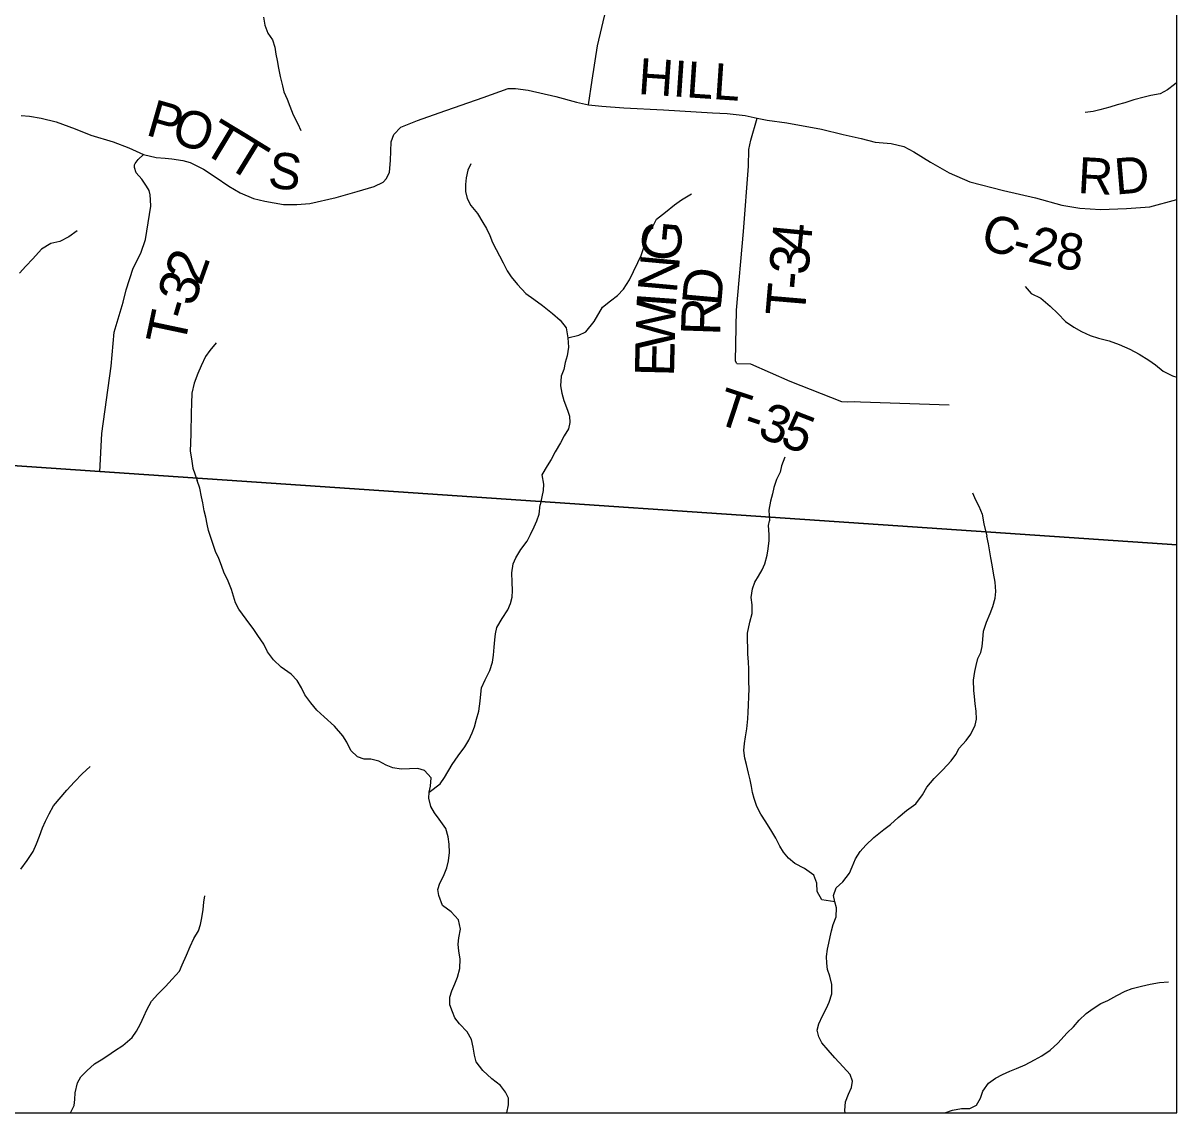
# Model space of a CAD drawing. Extents: x -139 to 835, y 0 to 440.
# Drawn here: x 550 to 607.6, y 185.1 to 239.4 of the extents above; entities that cross this region are included whole.
import ezdxf

# ---------------------------------------------------------------- set-up
doc = ezdxf.new("R2010")
doc.units = 0
for name, color, linetype in [('Default', 7, 'Continuous'), ('GM_X_County_Road', 7, 'Continuous'), ('GM_X_County_Road_Text', 7, 'Continuous'), ('GM_X_Minor_River', 7, 'Continuous'), ('GM_X_Township_Road', 7, 'Continuous'), ('GM_X_Township_Road_Text', 7, 'Continuous'), ('SH_Cut_Line', 7, 'Continuous')]:
    doc.layers.add(name, color=color, linetype=linetype)

msp = doc.modelspace()

# ---------------------------------------------------------------- linework, layer by layer
at = {"layer": 'Default'}
msp.add_lwpolyline([(533.705, 218.461), (553.865, 217.083), (607.596, 213.413), (607.596, 313.688), (599.523, 343.435), (599.103, 345.232), (598.348, 346.669), (593.771, 354.537), (573.292, 389.29), (556.01, 382.105), (544.238, 377.806)], dxfattribs=at)
msp.add_lwpolyline([(509.507, 185.075), (607.596, 185.075), (607.596, 213.413), (553.865, 217.083), (533.705, 218.461), (512.652, 220.106)], close=True, dxfattribs=at)
at = {"layer": 'GM_X_County_Road'}
msp.add_lwpolyline([(549.953, 234.836), (550.361, 234.805), (550.95, 234.711), (551.697, 234.514), (552.649, 234.171), (553.43, 233.859), (554.537, 233.522), (555.317, 233.224), (556.058, 232.895), (556.689, 232.74), (557.138, 232.704), (557.457, 232.675), (558.009, 232.591), (558.373, 232.484), (558.712, 232.328), (559.037, 232.161), (559.622, 231.779), (560.308, 231.311), (560.867, 230.977), (561.543, 230.702), (562.103, 230.559), (563.039, 230.392), (563.703, 230.392), (564.339, 230.448), (565.654, 230.742), (566.713, 231.051), (567.563, 231.302), (567.997, 231.508), (568.173, 231.699), (568.318, 232.009), (568.366, 232.597), (568.398, 233.525), (568.542, 233.893), (568.879, 234.261), (569.714, 234.585), (570.805, 234.968), (572.987, 235.734), (574.238, 236.176), (574.607, 236.19), (575.233, 236.102), (576.613, 235.778), (577.656, 235.498), (578.253, 235.362), (578.911, 235.303), (580.01, 235.222), (581.984, 235.126), (584.432, 234.964), (585.155, 234.929), (586.06, 234.833), (586.66, 234.71), (587.164, 234.597), (588.135, 234.466), (589.873, 234.151), (590.947, 233.882), (591.841, 233.688), (592.541, 233.509), (593.338, 233.435), (593.972, 233.285), (594.477, 233.031), (595.306, 232.509), (596.233, 231.971), (597.275, 231.524), (598.95, 231.091), (600.544, 230.732), (601.854, 230.363), (602.755, 230.212), (603.787, 230.151), (605.083, 230.192), (606.247, 230.282), (607.596, 230.652)], dxfattribs=at)
at = {"layer": 'GM_X_Minor_River'}
msp.add_line((607.596, 236.481), (607.475, 236.379), dxfattribs=at)
for points in [[(562.036, 239.735), (562.109, 239.351), (562.26, 238.941), (562.478, 238.615), (562.603, 238.242), (562.651, 237.894), (562.712, 237.581), (562.786, 237.197), (562.871, 236.776), (562.983, 236.319), (563.057, 236.018), (563.209, 235.657), (563.348, 235.307), (563.512, 234.874), (563.741, 234.416), (563.893, 234.09)], [(607.475, 236.379), (607.133, 236.119), (606.753, 235.919), (606.296, 235.828), (605.956, 235.76), (605.446, 235.621), (605.001, 235.47), (604.622, 235.366), (604.242, 235.251), (603.758, 235.124), (603.418, 235.031), (603.027, 234.988)], [(572.382, 232.427), (572.221, 232.117), (572.138, 231.734), (572.108, 231.399), (572.117, 231.039), (572.19, 230.702), (572.382, 230.352), (572.702, 229.953), (572.983, 229.494), (573.162, 229.193), (573.327, 228.843), (573.453, 228.506), (573.987, 227.493), (574.191, 227.095), (574.395, 226.793), (574.703, 226.405), (575.128, 225.957), (575.528, 225.677), (575.954, 225.361), (576.457, 224.959), (576.831, 224.631), (577.126, 224.244), (577.224, 223.74), (577.257, 223.272), (577.186, 222.853), (577.078, 222.518), (577.008, 222.171), (576.887, 221.824), (576.854, 221.345), (576.915, 220.985), (577.015, 220.612), (577.191, 220.142), (577.291, 219.829), (577.314, 219.517), (577.244, 219.206), (577.031, 218.849), (576.858, 218.503), (576.591, 218.062), (576.378, 217.668), (576.179, 217.359), (575.925, 216.906), (576.01, 216.437), (575.98, 216.126), (575.841, 215.419)], [(577.224, 223.74), (577.76, 223.878), (578.114, 224.042), (578.537, 224.565), (578.937, 225.28), (579.345, 225.588), (579.688, 225.86), (579.991, 226.18), (580.284, 226.645), (580.498, 227.051), (580.699, 227.504), (580.873, 227.85), (581.008, 228.244), (581.117, 228.591), (581.212, 228.914), (581.465, 229.331), (581.639, 229.665), (582.086, 230.02), (582.534, 230.387), (582.889, 230.623), (583.388, 230.929)], [(552.739, 229.089), (552.331, 228.782), (551.872, 228.547), (551.428, 228.444), (550.955, 228.161), (550.532, 227.686), (550.189, 227.318), (549.859, 226.974)], [(600.023, 226.3), (600.332, 225.961), (600.811, 225.716), (601.275, 225.327), (601.648, 224.952), (602.034, 224.564), (602.447, 224.283), (602.836, 224.063), (603.276, 223.855), (603.692, 223.73), (604.224, 223.592), (604.717, 223.419), (605.248, 223.174), (605.714, 222.929), (606.193, 222.636), (606.529, 222.392), (606.916, 222.088), (607.369, 221.844), (607.596, 221.783)], [(559.68, 223.498), (559.362, 223.117), (559.137, 222.808), (558.935, 222.354), (558.761, 221.96), (558.586, 221.483), (558.462, 220.98), (558.442, 220.465), (558.424, 220.009), (558.41, 218.978), (558.391, 218.486), (558.386, 218.103), (558.458, 217.586), (558.506, 217.25), (558.734, 216.628)], [(588.043, 217.794), (587.881, 217.364), (587.799, 217.041), (587.625, 216.671), (587.489, 216.277), (587.42, 215.966), (587.324, 215.595), (587.24, 215.14), (587.274, 214.612)], [(566.729, 202.84), (566.39, 203.153), (566.194, 203.574), (565.985, 203.886), (565.58, 204.367), (565.057, 204.835), (564.704, 205.172), (564.391, 205.533), (564.09, 205.929), (563.934, 206.29), (563.712, 206.65), (563.424, 206.963), (562.915, 207.311), (562.536, 207.684), (562.235, 208.08), (562.052, 208.465), (561.752, 208.886), (561.556, 209.186), (561.177, 209.703), (560.811, 210.208), (560.641, 210.532), (560.432, 211.181), (560.237, 211.686), (560.08, 211.998), (559.936, 212.383), (559.806, 212.731), (559.636, 213.092), (559.518, 213.44), (559.388, 213.825), (559.296, 214.137), (559.218, 214.45), (559.153, 214.798), (559.075, 215.111), (559.009, 215.507), (558.944, 215.82), (558.853, 216.252), (558.734, 216.628)], [(597.403, 216.014), (597.555, 215.665), (597.708, 215.351), (597.885, 214.953), (597.97, 214.473), (598.121, 213.846)], [(570.297, 201.074), (570.846, 201.494), (571.056, 201.806), (571.448, 202.455), (571.749, 202.888), (572.076, 203.345), (572.272, 203.669), (572.442, 204.03), (572.56, 204.33), (572.652, 204.726), (572.769, 205.123), (572.848, 205.616), (572.874, 205.964), (572.914, 206.289), (573.097, 206.685), (573.332, 207.142), (573.45, 207.562), (573.503, 207.911), (573.542, 208.307), (573.568, 208.68), (573.608, 208.98), (573.673, 209.293), (573.935, 209.738), (574.223, 210.17), (574.353, 210.483), (574.432, 210.807), (574.458, 211.143), (574.445, 211.552), (574.419, 212.021), (574.485, 212.465), (574.616, 212.766), (574.877, 213.186), (575.191, 213.595), (575.348, 213.931), (575.531, 214.316), (575.675, 214.616), (575.78, 214.953), (575.841, 215.419)], [(590.529, 195.603), (589.889, 195.711), (589.654, 196.12), (589.628, 196.541), (589.484, 196.937), (589.027, 197.262), (588.543, 197.514), (588.217, 197.791), (587.981, 198.091), (587.786, 198.392), (587.59, 198.776), (587.394, 199.113), (587.093, 199.593), (586.845, 199.978), (586.636, 200.363), (586.506, 200.759), (586.427, 201.06), (586.375, 201.36), (586.31, 201.685), (586.232, 202.033), (586.127, 202.454), (586.049, 202.766), (585.997, 203.151), (586.023, 203.499), (586.076, 203.836), (586.141, 204.244), (586.194, 204.737), (586.207, 205.062), (586.22, 205.41), (586.246, 205.843), (586.26, 206.227), (586.247, 206.576), (586.247, 207.225), (586.221, 207.561), (586.195, 207.982), (586.195, 208.306), (586.169, 208.631), (586.182, 209.015), (586.3, 209.556), (586.405, 209.989), (586.405, 210.421), (586.366, 210.794), (586.419, 211.214), (586.537, 211.551), (586.72, 211.851), (586.903, 212.176), (587.034, 212.476), (587.152, 212.897), (587.204, 213.221), (587.256, 213.63), (587.257, 213.93), (587.231, 214.375), (587.274, 214.612)], [(592.478, 198.824), (592.975, 199.208), (593.302, 199.473), (593.694, 199.809), (594.1, 200.17), (594.57, 200.494), (594.911, 200.939), (595.12, 201.335), (595.486, 201.756), (595.918, 202.2), (596.336, 202.633), (596.572, 202.957), (596.742, 203.27), (597.082, 203.654), (597.317, 203.967), (597.54, 204.424), (597.605, 204.724), (597.579, 205.121), (597.54, 205.493), (597.501, 205.854), (597.462, 206.154), (597.449, 206.659), (597.515, 207.103), (597.58, 207.404), (597.659, 207.74), (597.816, 208.053), (597.881, 208.353), (597.907, 208.69), (597.947, 209.11), (598.104, 209.567), (598.287, 209.988), (598.418, 210.348), (598.536, 210.757), (598.562, 211.081), (598.523, 211.55), (598.445, 212.007), (598.38, 212.415), (598.315, 212.764), (598.249, 213.16), (598.197, 213.461), (598.121, 213.846)], [(574.174, 185.075), (574.251, 185.474), (574.251, 185.81), (574.107, 186.111), (573.859, 186.447), (573.428, 186.784), (572.984, 187.192), (572.644, 187.625), (572.553, 187.95), (572.487, 188.358), (572.409, 188.743), (572.2, 189.115), (571.808, 189.512), (571.586, 189.825), (571.456, 190.125), (571.338, 190.474), (571.338, 190.846), (571.43, 191.171), (571.587, 191.519), (571.705, 191.856), (571.836, 192.276), (571.849, 192.757), (571.771, 193.142), (571.745, 193.49), (571.784, 193.803), (571.863, 194.247), (571.758, 194.704), (571.393, 195.113), (570.961, 195.425), (570.779, 195.918), (570.726, 196.218), (570.831, 196.531), (571.014, 196.879), (571.184, 197.3), (571.263, 197.648), (571.315, 198.069), (571.289, 198.49), (571.25, 198.85), (571.133, 199.259), (570.793, 199.728), (570.558, 200.04), (570.375, 200.364), (570.284, 200.773), (570.297, 201.074), (570.363, 201.374), (570.402, 201.795), (570.062, 202.167), (569.736, 202.251), (568.899, 202.227), (568.481, 202.287), (568.154, 202.42), (567.788, 202.624), (567.383, 202.732), (567.056, 202.732), (566.729, 202.84)], [(549.93, 197.243), (550.244, 197.663), (550.545, 198.12), (550.715, 198.492), (550.859, 198.889), (551.016, 199.297), (551.16, 199.634), (551.343, 199.994), (551.566, 200.403), (552.22, 201.172), (552.612, 201.593), (552.991, 201.989), (553.396, 202.362)], [(591.042, 185.075), (591.034, 185.195), (591.073, 185.628), (591.217, 186.012), (591.361, 186.337), (591.414, 186.661), (591.296, 186.986), (590.957, 187.37), (590.526, 187.827), (590.199, 188.2), (589.885, 188.572), (589.729, 188.873), (589.65, 189.209), (589.742, 189.522), (589.912, 189.918), (590.121, 190.303), (590.252, 190.604), (590.383, 191.024), (590.383, 191.481), (590.279, 191.901), (590.175, 192.238), (590.136, 192.539), (590.123, 192.875), (590.175, 193.248), (590.228, 193.548), (590.293, 193.861), (590.372, 194.161), (590.45, 194.473), (590.607, 194.858), (590.621, 195.303), (590.529, 195.603), (590.464, 195.928), (590.595, 196.312), (590.935, 196.601), (591.262, 197.033), (591.393, 197.346), (591.563, 197.754), (591.798, 198.115), (592.073, 198.427), (592.478, 198.824)], [(552.386, 185.075), (552.421, 185.116), (552.592, 185.441), (552.631, 185.753), (552.644, 186.077), (552.762, 186.582), (552.932, 186.883), (553.22, 187.183), (553.599, 187.532), (553.939, 187.724), (554.279, 187.94), (554.606, 188.168), (555.024, 188.445), (555.482, 188.841), (555.704, 189.154), (555.9, 189.526), (556.071, 189.887), (556.215, 190.223), (556.45, 190.644), (556.764, 190.992), (557.143, 191.377), (557.483, 191.75), (557.849, 192.146), (557.98, 192.458), (558.19, 192.939), (558.373, 193.372), (558.569, 193.78), (558.791, 194.165), (558.896, 194.477), (558.962, 194.814), (559.027, 195.222), (559.066, 195.595), (559.106, 195.907)], [(596.016, 185.075), (596.406, 185.218), (596.851, 185.291), (597.269, 185.303), (597.596, 185.459), (597.792, 185.807), (597.91, 186.156), (598.198, 186.564), (598.551, 186.805), (598.904, 186.997), (599.27, 187.153), (599.597, 187.285), (600.028, 187.478), (600.486, 187.718), (600.852, 187.922), (601.27, 188.199), (601.649, 188.559), (602.12, 189.064), (602.434, 189.376), (602.722, 189.701), (603.062, 190.037), (603.415, 190.278), (603.807, 190.53), (604.147, 190.686), (604.592, 190.927), (605.01, 191.143), (605.363, 191.287), (605.834, 191.407), (606.265, 191.503), (606.723, 191.575), (607.18, 191.623)]]:
    msp.add_lwpolyline(points, dxfattribs=at)
at = {"layer": 'GM_X_Township_Road'}
for points in [[(578.253, 235.362), (578.43, 236.599), (578.703, 238.314), (579.633, 242.274)], [(585.648, 222.466), (585.573, 222.576), (585.634, 225.122), (585.985, 229.045), (586.229, 232.315), (586.25, 233.146), (586.336, 233.601), (586.66, 234.71)], [(553.873, 217.066), (553.969, 218.967), (554.436, 222.329), (554.592, 224.024), (555.041, 225.521), (555.193, 226.142), (555.528, 227.223), (555.921, 227.971), (556.146, 228.649), (556.276, 229.485), (556.422, 230.317), (556.397, 230.633), (556.384, 230.872), (556.331, 231.093), (556.195, 231.308), (555.961, 231.666), (555.688, 231.982), (555.61, 232.251), (555.61, 232.37), (555.636, 232.448), (555.792, 232.639), (556.058, 232.895)], [(585.648, 222.466), (586.327, 222.445), (588.294, 221.576), (590.86, 220.57), (591.159, 220.547), (591.532, 220.57), (591.806, 220.547), (596.24, 220.41)]]:
    msp.add_lwpolyline(points, dxfattribs=at)
at = {"layer": 'SH_Cut_Line'}
for points in [[(607.596, 213.413), (607.596, 400.079), (373.24, 400.079), (373.24, 228.621), (390.412, 227.867), (402.968, 227.036), (407.389, 226.858), (433.728, 225.419), (479.461, 222.215), (494.743, 221.147), (512.652, 220.106), (533.705, 218.461), (553.865, 217.083)], [(373.24, 228.621), (373.24, 185.075), (607.596, 185.075), (607.596, 213.413), (553.865, 217.083), (533.705, 218.461), (512.652, 220.106), (494.743, 221.147), (479.461, 222.215), (433.728, 225.419), (407.389, 226.858), (402.968, 227.036), (390.412, 227.867)]]:
    msp.add_lwpolyline(points, close=True, dxfattribs=at)

# ---------------------------------------------------------------- texts
at = {"layer": 'GM_X_County_Road_Text'}
for s, height, rotation, p in [('HILL', 1.8004, 356.11014, (580.691, 235.914)), ('P', 1.852, 344.0902, (556.11, 233.881)), ('O', 1.862, 342.45496, (557.357, 233.526)), ('T', 1.939, 328.8713, (558.87, 233.064)), ('T', 1.941, 328.44328, (560.09, 232.327)), ('S', 1.809, 352.81404, (562.206, 231.266)), ('R', 1.799, 356.75317, (602.622, 230.975)), ('D', 1.803, 4.88359, (604.552, 230.889)), ('C', 1.845, 345.20246, (597.733, 228.205)), ('2', 1.84, 346.1434, (600.088, 227.585)), ('-', 1.844, 345.36043, (599.284, 227.795)), ('8', 1.812, 352.0685, (601.487, 227.253))]:
    msp.add_text(s, height=height, rotation=rotation, dxfattribs=at).set_placement(p)
at = {"layer": 'GM_X_Township_Road_Text'}
for s, height, rotation, p in [('G', 1.959, 84.73904, (582.79, 227.5)), ('4', 1.959, 84.52735, (589.298, 227.942)), ('2', 1.971, 70.42928, (558.907, 226.301)), ('3', 1.959, 85.03332, (589.202, 226.843)), ('N', 1.959, 84.73904, (582.645, 225.925)), ('3', 1.97, 71.4937, (558.556, 225.251)), ('D', 1.959, 84.91802, (584.857, 225.285)), ('-', 1.959, 85.08754, (589.139, 226.107)), ('T', 1.959, 85.1107, (589.024, 224.768)), ('W', 1.958, 88.56747, (582.543, 223.137)), ('I', 1.959, 85.94811, (582.594, 225.198)), ('T', 1.964, 78.06575, (558.082, 223.268)), ('-', 1.968, 73.70753, (558.353, 224.555)), ('R', 1.958, 88.06836, (584.809, 223.834)), ('E', 1.958, 88.62653, (582.51, 221.794)), ('T', 1.865, 341.87225, (584.499, 219.518)), ('3', 1.876, 340.1691, (586.617, 218.815)), ('5', 1.883, 338.88753, (587.728, 218.414)), ('-', 1.869, 341.18509, (585.872, 219.068))]:
    msp.add_text(s, height=height, rotation=rotation, dxfattribs=at).set_placement(p)

doc.saveas('drawing.dxf')
